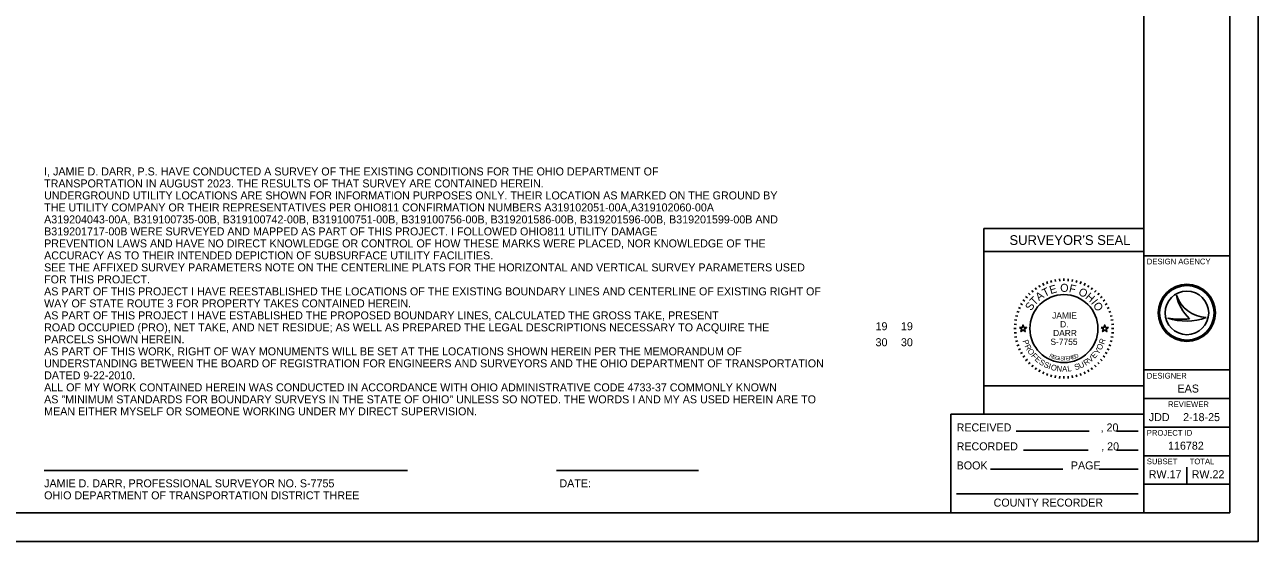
# Model space of a CAD drawing. Extents: x 135685 to 142485, y 474819 to 479219.
# Drawn here: x 138170 to 142485, y 474819 to 476628 of the extents above; entities that cross this region are included whole.
import ezdxf

# ---------------------------------------------------------------- set-up
doc = ezdxf.new("R2010")
doc.units = 0
for name, color, linetype in [('Default', 7, 'Continuous'), ('DV_X_Property_Line', 7, 'Continuous'), ('GE_X_Alignment_100_Curve_Data', 7, 'Continuous'), ('GE_X_Alignment_100_Distances', 7, 'Continuous'), ('GE_X_Alignment_100_Stations', 7, 'Continuous'), ('RW_X_Esmt_SH', 7, 'Continuous')]:
    doc.layers.add(name, color=color, linetype=linetype)

msp = doc.modelspace()

# ---------------------------------------------------------------- linework, layer by layer
at = {"layer": 'Default'}
for p, q in [((138237.7, 475067.8), (139508.2, 475067.8)), ((140029.7, 475067.8), (140527, 475067.8))]:
    msp.add_line(p, q, dxfattribs=at)
at = {"layer": 'DV_X_Property_Line'}
for p, q in [((142084.7, 474919.3), (142084.7, 479119.3)), ((142084.7, 475819.3), (142384.7, 475819.3)), ((142084.7, 475419.3), (142384.7, 475419.3)), ((142084.7, 475319.3), (142384.7, 475319.3)), ((142084.7, 475219.3), (142384.7, 475219.3)), ((142084.7, 475119.3), (142384.7, 475119.3)), ((142084.7, 475019.3), (142384.7, 475019.3))]:
    msp.add_line(p, q, dxfattribs=at)
msp.add_lwpolyline([(135984.7, 479119.3), (142384.7, 479119.3), (142384.7, 474919.3), (135984.7, 474919.3)], close=True, dxfattribs=at)
at = {"layer": 'GE_X_Alignment_100_Curve_Data'}
for p, q in [((141409.5, 474919.3), (141409.5, 475264.2)), ((141409.5, 475264.2), (142084.7, 475264.2)), ((142084.7, 475264.2), (142084.7, 474919.3)), ((141638, 475205.2), (141892.5, 475205.2)), ((141989.2, 475205.2), (142064.7, 475205.2)), ((141663.1, 475138.5), (141889.3, 475138.5)), ((141989.2, 475138.5), (142064.7, 475138.5)), ((141547.4, 475071.8), (141800.6, 475071.8)), ((141928.6, 475071.8), (142064.7, 475071.8)), ((141429.5, 474986.2), (142064.7, 474986.2))]:
    msp.add_line(p, q, dxfattribs=at)
at = {"layer": 'GE_X_Alignment_100_Distances'}
for p, q in [((142084.7, 475914.2), (141524.7, 475914.2)), ((141524.7, 475914.2), (141524.7, 475264.2)), ((142084.7, 475264.2), (142084.7, 475914.2)), ((142084.7, 475834.2), (141524.7, 475834.2)), ((142198.2, 475681.3), (142198.2, 475681.3)), ((142234.7, 475619.3), (142234.7, 475619.3)), ((142168.2, 475601.2), (142168.2, 475601.2)), ((142302.2, 475603), (142302.2, 475603)), ((142084.7, 475264.2), (141524.7, 475264.2)), ((142234.7, 475019.3), (142234.7, 475079.3))]:
    msp.add_line(p, q, dxfattribs=at)
msp.add_lwpolyline([(142084.7, 475264.2), (142084.7, 475364.2), (141524.7, 475364.2), (141524.7, 475264.2)], close=True, dxfattribs=at)
for radius in [100, 95.4, 95.4, 76.4]:
    msp.add_circle((142234.7, 475619.3), radius, dxfattribs=at)
for centre, radius, start, end in [((142307.9, 475718.9), 116, 198.9257, 198.9319), ((142354.1, 475713.4), 159.1, 191.6379, 191.6421), ((142307.9, 475718.9), 116, 198.9319, 267.1657), ((142354.1, 475713.4), 159.1, 191.6421, 226.0947), ((142232.6, 475793.3), 202.6, 251.4576, 290.0832), ((142214.3, 475850.2), 253.2, 259.4964, 259.4995), ((142232.6, 475793.3), 202.6, 251.4527, 251.4576), ((142214.3, 475850.2), 253.2, 259.4995, 276.6672)]:
    msp.add_arc(centre, radius, start, end, dxfattribs=at)
at = {"layer": 'GE_X_Alignment_100_Stations'}
msp.add_lwpolyline([(135684.7, 474819.3), (142484.7, 474819.3), (142484.7, 479219.3), (135684.7, 479219.3)], close=True, dxfattribs=at)
at = {"layer": 'RW_X_Esmt_SH'}
for p, q in [((141774.3, 475736.5), (141775.7, 475728.6)), ((141789.5, 475738.5), (141790.2, 475730.5)), ((141804.7, 475739.2), (141804.7, 475731.2)), ((141820, 475738.5), (141819.3, 475730.5)), ((141835.1, 475736.5), (141833.7, 475728.6)), ((141692.2, 475698.2), (141697.4, 475692.1)), ((141704.4, 475707.5), (141708.9, 475701)), ((141717.2, 475715.7), (141721.2, 475708.8)), ((141730.8, 475722.8), (141734.2, 475715.5)), ((141744.9, 475728.6), (141747.6, 475721.1)), ((141759.4, 475733.2), (141761.5, 475725.5)), ((141850, 475733.2), (141848, 475725.5)), ((141864.6, 475728.6), (141861.8, 475721.1)), ((141878.7, 475722.8), (141875.3, 475715.5)), ((141892.2, 475715.7), (141888.2, 475708.8)), ((141905.1, 475707.5), (141900.5, 475701)), ((141917.2, 475698.2), (141912.1, 475692.1)), ((141653.2, 475651.7), (141660.1, 475647.7)), ((141661.4, 475664.5), (141667.9, 475660)), ((141670.7, 475676.7), (141676.8, 475671.5)), ((141681, 475687.9), (141686.6, 475682.3)), ((141928.5, 475687.9), (141922.8, 475682.3)), ((141938.8, 475676.7), (141932.7, 475671.5)), ((141948.1, 475664.5), (141941.5, 475660)), ((141956.3, 475651.7), (141949.4, 475647.7)), ((141635.7, 475609.5), (141643.4, 475607.4)), ((141640.3, 475624), (141647.8, 475621.3)), ((141646.1, 475638.1), (141653.4, 475634.8)), ((141963.3, 475638.1), (141956.1, 475634.8)), ((141969.2, 475624), (141961.7, 475621.3)), ((141973.8, 475609.5), (141966, 475607.4)), ((141629.7, 475564.2), (141637.7, 475564.2)), ((141630.4, 475579.4), (141638.4, 475578.7)), ((141632.4, 475594.6), (141640.3, 475593.2)), ((141977.1, 475594.6), (141969.2, 475593.2)), ((141979.1, 475579.4), (141971.1, 475578.7)), ((141979.7, 475564.2), (141971.7, 475564.2)), ((141630.4, 475548.9), (141638.4, 475549.6)), ((141632.4, 475533.8), (141640.3, 475535.2)), ((141635.7, 475518.9), (141643.4, 475521)), ((141973.8, 475518.9), (141966, 475521)), ((141977.1, 475533.8), (141969.2, 475535.2)), ((141979.1, 475548.9), (141971.1, 475549.6)), ((141640.3, 475504.3), (141647.8, 475507.1)), ((141646.1, 475490.2), (141653.4, 475493.6)), ((141653.2, 475476.7), (141660.1, 475480.7)), ((141956.3, 475476.7), (141949.4, 475480.7)), ((141963.3, 475490.2), (141956.1, 475493.6)), ((141969.2, 475504.3), (141961.7, 475507.1)), ((141661.4, 475463.8), (141667.9, 475468.4)), ((141670.7, 475451.7), (141676.8, 475456.8)), ((141681, 475440.4), (141686.6, 475446.1)), ((141692.2, 475430.1), (141697.4, 475436.2)), ((141917.2, 475430.1), (141912.1, 475436.2)), ((141928.5, 475440.4), (141922.8, 475446.1)), ((141938.8, 475451.7), (141932.7, 475456.8)), ((141948.1, 475463.8), (141941.5, 475468.4)), ((141704.4, 475420.8), (141708.9, 475427.4)), ((141717.2, 475412.6), (141721.2, 475419.5)), ((141730.8, 475405.6), (141734.2, 475412.8)), ((141744.9, 475399.7), (141747.6, 475407.2)), ((141759.4, 475395.1), (141761.5, 475402.9)), ((141774.3, 475391.8), (141775.7, 475399.7)), ((141789.5, 475389.8), (141790.2, 475397.8)), ((141804.7, 475389.2), (141804.7, 475397.2)), ((141820, 475389.8), (141819.3, 475397.8)), ((141835.1, 475391.8), (141833.7, 475399.7)), ((141850, 475395.1), (141848, 475402.9)), ((141864.6, 475399.7), (141861.8, 475407.2)), ((141878.7, 475405.6), (141875.3, 475412.8)), ((141892.2, 475412.6), (141888.2, 475419.5)), ((141905.1, 475420.8), (141900.5, 475427.4))]:
    msp.add_line(p, q, dxfattribs=at)
for points in [[(141649.5, 475568.2), (141658.8, 475568.2), (141661.7, 475577.1), (141664.6, 475568.2), (141674, 475568.2), (141666.4, 475562.6), (141669.3, 475553.7), (141661.7, 475559.2), (141654.1, 475553.7), (141657, 475562.6)], [(141935.5, 475568.2), (141944.8, 475568.2), (141947.7, 475577.1), (141950.6, 475568.2), (141960, 475568.2), (141952.4, 475562.6), (141955.3, 475553.7), (141947.7, 475559.2), (141940.1, 475553.7), (141943, 475562.6)]]:
    msp.add_lwpolyline(points, close=True, dxfattribs=at)
msp.add_circle((141804.7, 475564.2), 119, dxfattribs=at)

# ---------------------------------------------------------------- texts
at = {"layer": 'Default'}
for s, p in [('I, JAMIE D. DARR, P.S. HAVE CONDUCTED A SURVEY OF THE EXISTING CONDITIONS FOR THE OHIO DEPARTMENT OF', (138237.7, 476100.5)), ('TRANSPORTATION IN AUGUST 2023. THE RESULTS OF THAT SURVEY ARE CONTAINED HEREIN.', (138237.7, 476058.5)), ('UNDERGROUND UTILITY LOCATIONS ARE SHOWN FOR INFORMATION PURPOSES ONLY. THEIR LOCATION AS MARKED ON THE GROUND BY ', (138237.7, 476016.5)), ('THE UTILITY COMPANY OR THEIR REPRESENTATIVES PER OHIO811 CONFIRMATION NUMBERS A319102051-00A,A319102060-00A', (138237.7, 475974.5)), ('A319204043-00A, B319100735-00B, B319100742-00B, B319100751-00B, B319100756-00B, B319201586-00B, B319201596-00B, B319201599-00B AND', (138237.7, 475932.5)), ('B319201717-00B WERE SURVEYED AND MAPPED AS PART OF THIS PROJECT. I FOLLOWED OHIO811 UTILITY DAMAGE', (138237.7, 475890.5)), ('PREVENTION LAWS AND HAVE NO DIRECT KNOWLEDGE OR CONTROL OF HOW THESE MARKS WERE PLACED, NOR KNOWLEDGE OF THE ', (138237.7, 475848.5)), ('ACCURACY AS TO THEIR INTENDED DEPICTION OF SUBSURFACE UTILITY FACILITIES.', (138237.7, 475806.5)), ('SEE THE AFFIXED SURVEY PARAMETERS NOTE ON THE CENTERLINE PLATS FOR THE HORIZONTAL AND VERTICAL SURVEY PARAMETERS USED ', (138237.7, 475764.5)), ('FOR THIS PROJECT.', (138237.7, 475722.5)), ('AS PART OF THIS PROJECT I HAVE REESTABLISHED THE LOCATIONS OF THE EXISTING BOUNDARY LINES AND CENTERLINE OF EXISTING RIGHT OF ', (138237.7, 475680.5)), ('WAY OF STATE ROUTE 3 FOR PROPERTY TAKES CONTAINED HEREIN.', (138237.7, 475638.5)), ('AS PART OF THIS PROJECT I HAVE ESTABLISHED THE PROPOSED BOUNDARY LINES, CALCULATED THE GROSS TAKE, PRESENT', (138237.7, 475596.5)), ('ROAD OCCUPIED (PRO), NET TAKE, AND NET RESIDUE; AS WELL AS PREPARED THE LEGAL DESCRIPTIONS NECESSARY TO ACQUIRE THE', (138237.7, 475554.5)), ('PARCELS SHOWN HEREIN.', (138237.7, 475512.5)), ('AS PART OF THIS WORK, RIGHT OF WAY MONUMENTS WILL BE SET AT THE LOCATIONS SHOWN HEREIN PER THE MEMORANDUM OF ', (138237.7, 475470.5)), ('UNDERSTANDING BETWEEN THE BOARD OF REGISTRATION FOR ENGINEERS AND SURVEYORS AND THE OHIO DEPARTMENT OF TRANSPORTATION ', (138237.7, 475428.5)), ('DATED 9-22-2010.', (138237.7, 475386.5)), ('ALL OF MY WORK CONTAINED HEREIN WAS CONDUCTED IN ACCORDANCE WITH OHIO ADMINISTRATIVE CODE 4733-37 COMMONLY KNOWN', (138237.7, 475344.5)), ('AS "MINIMUM STANDARDS FOR BOUNDARY SURVEYS IN THE STATE OF OHIO" UNLESS SO NOTED. THE WORDS I AND MY AS USED HEREIN ARE TO', (138237.7, 475302.5)), ('MEAN EITHER MYSELF OR SOMEONE WORKING UNDER MY DIRECT SUPERVISION.', (138237.7, 475260.5)), ('JAMIE D. DARR, PROFESSIONAL SURVEYOR NO. S-7755                                                               ', (138237.7, 475008.5)), (' DATE:', (140029.7, 475008.5)), ('OHIO DEPARTMENT OF TRANSPORTATION DISTRICT THREE', (138237.7, 474966.5))]:
    msp.add_text(s, height=28, dxfattribs=at).set_placement(p)
at = {"layer": 'GE_X_Alignment_100_Curve_Data'}
for s, p in [('19', (141145.9, 475558.5)), ('19', (141234.7, 475558.5)), ('30', (141145.9, 475502.5)), ('30', (141234.7, 475502.5)), ('RECEIVED                              , 20', (141429.5, 475204.2)), ('RECORDED                            , 20', (141429.5, 475138.1)), ('BOOK                            PAGE', (141429.5, 475071.2)), ('COUNTY RECORDER', (141558.8, 474941))]:
    msp.add_text(s, height=28, dxfattribs=at).set_placement(p)
at = {"layer": 'GE_X_Alignment_100_Distances'}
for s, height, p in [("SURVEYOR'S SEAL", 34, (141614.3, 475857.2)), ('DESIGN AGENCY', 20, (142094.7, 475789.3)), ('DESIGNER', 20, (142094.7, 475389.3)), ('EAS', 28, (142202.1, 475340.3)), ('REVIEWER', 20, (142169.1, 475289.3)), ('JDD', 28, (142101.6, 475240.3)), ('2-18-25', 28, (142221.6, 475240.3)), ('PROJECT ID', 20, (142094.7, 475189.3)), ('116782', 28, (142168.9, 475140.3)), ('SUBSET', 20, (142094.7, 475089.3)), ('TOTAL', 20, (142244.7, 475089.3)), ('RW.17', 28, (142101.4, 475040.3)), ('RW.22', 28, (142251.6, 475040.3))]:
    msp.add_text(s, height=height, dxfattribs=at).set_placement(p)
at = {"layer": 'RW_X_Esmt_SH'}
for s, height, rotation, p in [('T', 28, 25.7167, (141737.1, 475674.5)), ('E', 28, 15.7571, (141758.4, 475684.9)), ('O', 28, 359.7812, (141791.7, 475693)), ('F', 28, 347.4362, (141820.9, 475692.5)), ('O', 28, 332.2586, (141852.7, 475684.5)), ('S', 28, 57.1924, (141690.3, 475624.5)), ('T', 28, 46.4344, (141702.4, 475643.5)), ('A', 28, 36.4747, (141717.4, 475659.8)), ('H', 28, 319.9136, (141877.4, 475671.4)), ('I', 28, 308.367, (141898, 475653.8)), ('O', 28, 303.1491, (141905.2, 475645.9)), ('P', 20, 289.7431, (141659.8, 475521)), ('R', 20, 70.983, (141944.9, 475507.5)), ('R', 20, 296.9802, (141666.6, 475502.7)), ('O', 20, 304.7158, (141675.4, 475485.7)), ('F', 20, 312.956, (141688.6, 475467.3)), ('R', 14, 334.487, (141752.2, 475465.2)), ('E', 20, 48.2687, (141912, 475457.6)), ('Y', 20, 55.5058, (141924.7, 475472.2)), ('O', 20, 62.7428, (141934.7, 475486.8)), ('E', 20, 319.6885, (141700.9, 475454.3)), ('S', 20, 326.9255, (141715.8, 475441.9)), ('S', 20, 334.1626, (141731.9, 475431.7)), ('I', 20, 341.3997, (141748.5, 475423.8)), ('O', 20, 345.1351, (141757.1, 475420.6)), ('E', 14, 341.04, (141762.9, 475460.2)), ('G', 14, 347.4752, (141773, 475456.5)), ('N', 20, 353.3752, (141777.9, 475415.3)), ('I', 14, 353.7858, (141786.5, 475453.5)), ('S', 14, 356.8926, (141791.9, 475452.7)), ('A', 20, 1.1108, (141798.6, 475413)), ('T', 14, 3.0061, (141801.9, 475451.9)), ('E', 14, 6.0117, (141812.5, 475452.4)), ('L', 20, 8.3479, (141818, 475413.5)), ('R', 14, 11.9184, (141823.2, 475453.6)), ('E', 14, 17.6836, (141834.7, 475456.2)), ('D', 14, 23.3052, (141844.9, 475459.6)), ('S', 20, 18.3234, (141844.8, 475418.4)), ('U', 20, 25.5604, (141861.4, 475423.9)), ('R', 20, 33.296, (141881, 475433.6)), ('V', 20, 41.0316, (141897, 475444.3))]:
    msp.add_text(s, height=height, rotation=rotation, dxfattribs=at).set_placement(p)
for s, p in [('JAMIE', (141763.5, 475599.2)), ('D.', (141791.4, 475568.5)), ('S-7755', (141757.6, 475507.2)), ('DARR', (141766.9, 475537.8))]:
    msp.add_text(s, height=22, dxfattribs=at).set_placement(p)

doc.saveas('drawing.dxf')
